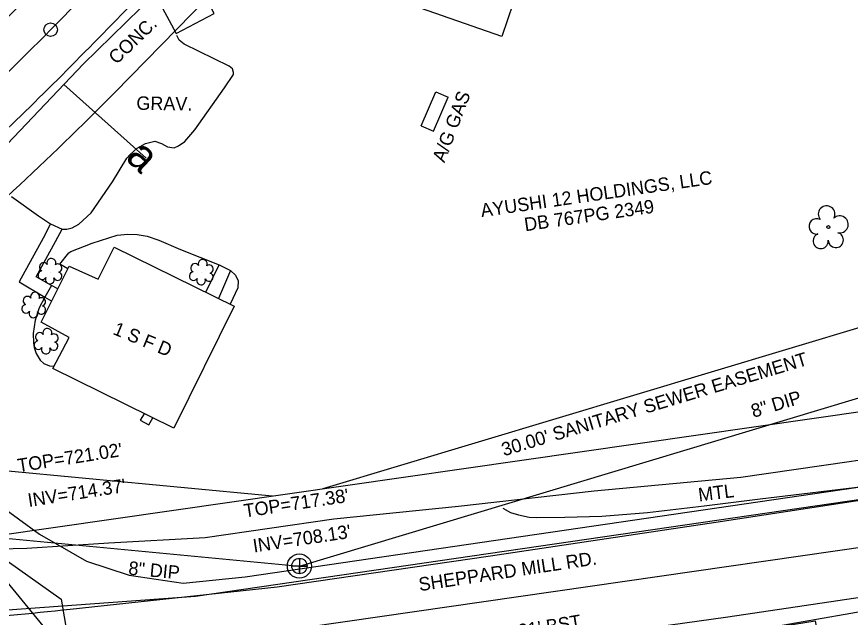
# Model space of a CAD drawing. Extents: x 1645945 to 2447332, y 713118 to 970361.
# Drawn here: x 1646361.8 to 1646547.8, y 969454.4 to 969588.4 of the extents above; entities that cross this region are included whole.
import ezdxf

# ---------------------------------------------------------------- set-up
doc = ezdxf.new("R2010")
doc.units = 0
for name, color, linetype in [('Exist Building', 7, 'Continuous'), ('Exist Building Text', 7, 'Continuous'), ('Exist Guardrail', 7, 'Continuous'), ('Exist Guardrail Text', 7, 'Continuous'), ('Exist Horizontal Alignment', 7, 'Continuous'), ('Exist Horizontal Alignment Station Label', 7, 'Continuous'), ('Exist Other Culture AG Tank', 7, 'Continuous'), ('Exist Other Culture AG Tank Text', 7, 'Continuous'), ('Exist Other Culture Area Outline', 7, 'Continuous'), ('Exist Other Culture Area Outline Text', 7, 'Continuous'), ('Exist Property Deed Book Text', 7, 'Continuous'), ('Exist Property Owner Text', 7, 'Continuous'), ('Exist Right of Way Easement Line', 7, 'Continuous'), ('Exist Right of Way Easement Line Text', 7, 'Continuous'), ('Exist Right of Way Line', 7, 'Continuous'), ('Exist Roads EOP', 7, 'Continuous'), ('Exist Roads EOP Text', 7, 'Continuous'), ('Exist Roads Soil', 7, 'Continuous'), ('Exist Roads Soil Text', 7, 'Continuous'), ('Exist Structure Minor Pipes RCP 18 Inch', 7, 'Continuous'), ('Exist Utilities Sanitary Sewer Manhole CELL', 7, 'Continuous'), ('Exist Utilities Sanitary Sewer Manhole Top Elevation', 7, 'Continuous'), ('Exist Utilities Sanitary Sewer UG Line', 7, 'Continuous'), ('Exist Utilities Sanitary Sewer UG Line Invert Elevation', 7, 'Continuous'), ('Exist Utilities Sanitary Sewer UG Line Text', 7, 'Continuous'), ('Exist Utilities Telephone UG Cable SUE LOS C', 7, 'Continuous'), ('Exist Utilities Telephone UG Conduit SUE LOS B', 7, 'Continuous'), ('Exist Utilities Telephone UG FO SUE LOS C', 7, 'Continuous'), ('Exist Utilities Water Meter CELL', 7, 'Continuous'), ('Exist Utilities Water UG Line SUE LOS B', 7, 'Continuous'), ('Exist Utilities Water UG Line SUE LOS C', 7, 'Continuous'), ('Exist Vegetation Shrub CELL', 7, 'Continuous'), ('Exist Vegetation Tree CELL', 7, 'Continuous')]:
    doc.layers.add(name, color=color, linetype=linetype)

msp = doc.modelspace()

# ---------------------------------------------------------------- linework, layer by layer
at = {"layer": 'Exist Building'}
for points in [[(1646470.02, 969583.99), (1646438.6, 969594.98), (1646445.1, 969613.68), (1646476.38, 969602.62)], [(1646410.32, 969523.79), (1646396.83, 969496.56), (1646369.82, 969509.94), (1646373.44, 969516.79), (1646367.24, 969520.22), (1646373.48, 969532.73), (1646379.92, 969529.81), (1646383.54, 969536.96)]]:
    msp.add_lwpolyline(points, close=True, dxfattribs=at)
at = {"layer": 'Exist Guardrail'}
for points in [[(1646470.26, 969478.73), (1646471.95, 969477.82), (1646473.74, 969477.24), (1646476.14, 969476.78), (1646477.86, 969476.66), (1646484.1, 969476.72), (1646492.35, 969476.96), (1646502.55, 969477.78), (1646515.16, 969479.3), (1646527.66, 969480.85), (1646552.44, 969483.79), (1646583.27, 969487.45), (1646605.12, 969490.42), (1646611.18, 969491.34), (1646616.77, 969492.33)], [(1646620.15, 969467.73), (1646608.6, 969466.17), (1646598.74, 969464.76), (1646580.79, 969461.39), (1646556.85, 969456.85), (1646531.28, 969452.35), (1646475.87, 969443.26), (1646432.85, 969436.42), (1646414.57, 969433.47), (1646402.18, 969431.21), (1646389.91, 969428.75), (1646383.65, 969427.16), (1646377.73, 969425.47), (1646371.72, 969423.8), (1646365.89, 969422.14), (1646363.88, 969421.49)]]:
    msp.add_lwpolyline(points, dxfattribs=at)
at = {"layer": 'Exist Horizontal Alignment'}
for p, q in [((1646418.81, 969635.96), (1646369.34, 969585.48)), ((1646298.92, 969433.93), (1647141.43, 969555.05))]:
    msp.add_line(p, q, dxfattribs=at)
msp.add_arc((1645951.5, 969994.91), 585, 309.61403, 315.58305, dxfattribs=at)
at = {"layer": 'Exist Horizontal Alignment Station Label'}
msp.add_circle((1646369.34, 969585.48), 1.5, dxfattribs=at)
at = {"layer": 'Exist Other Culture AG Tank'}
for p, q in [((1646452, 969564.02), (1646455.31, 969571.6)), ((1646454.75, 969562.82), (1646458.05, 969570.4)), ((1646455.31, 969571.6), (1646458.05, 969570.4)), ((1646452, 969564.02), (1646454.75, 969562.82))]:
    msp.add_line(p, q, dxfattribs=at)
at = {"layer": 'Exist Other Culture Area Outline'}
msp.add_lwpolyline([(1646397.32, 969584.61), (1646405.82, 969589.12), (1646401.24, 969597.74), (1646392.75, 969593.23), (1646397.32, 969584.61)], close=True, dxfattribs=at)
for points in [[(1646369.28, 969542.17), (1646367.71, 969538.98), (1646362.33, 969529.26), (1646368.06, 969525.79)], [(1646369.54, 969528.39), (1646366.13, 969530.36), (1646370.41, 969538.25), (1646371.95, 969540.99)], [(1646373.19, 969532.16), (1646371.37, 969533.21), (1646373.38, 969535.72), (1646373.85, 969536.04), (1646378.6, 969537.84), (1646384.18, 969539.65), (1646386.53, 969539.88), (1646388.64, 969539.79), (1646390.88, 969539.43), (1646393.47, 969538.54), (1646398.32, 969536.45), (1646406.93, 969533.01)], [(1646403.97, 969526.91), (1646406.93, 969533.01), (1646409.48, 969531.75), (1646406.81, 969525.51)], [(1646409.48, 969531.75), (1646410.61, 969530.76), (1646411.18, 969529.43), (1646411.1, 969527.9), (1646409.37, 969524.26)], [(1646370.95, 969527.66), (1646369.54, 969528.39), (1646368.06, 969525.79), (1646369.61, 969524.96)], [(1646368.06, 969525.79), (1646366.81, 969523.45), (1646365.88, 969520.72), (1646365.44, 969517.72), (1646365.5, 969515.61), (1646365.69, 969514.59), (1646366.1, 969513.23), (1646367.03, 969511.79), (1646367.85, 969511.05), (1646369.09, 969510.49), (1646370.08, 969510.44)], [(1646390.22, 969499.83), (1646389.31, 969498.38), (1646391.22, 969497.33), (1646392.13, 969498.89)]]:
    msp.add_lwpolyline(points, dxfattribs=at)
at = {"layer": 'Exist Right of Way Easement Line'}
for points in [[(1646430.19, 969483.11), (1646568.82, 969524.75)], [(1646336.92, 969489.25), (1646418.86, 969481.48)]]:
    msp.add_lwpolyline(points, dxfattribs=at)
at = {"layer": 'Exist Right of Way Line'}
for p, q in [((1646433.09, 969621.96), (1646383.63, 969571.48)), ((1646341.77, 969470.4), (1647145.86, 969586))]:
    msp.add_line(p, q, dxfattribs=at)
msp.add_arc((1645951.5, 969994.91), 605, 309.61403, 315.58305, dxfattribs=at)
at = {"layer": 'Exist Roads EOP'}
for points in [[(1646615.85, 969490.95), (1646565.02, 969482.74), (1646517.77, 969475.58), (1646467.5, 969468.02), (1646419.87, 969461.1), (1646373.7, 969456.15)], [(1646618.95, 969468.72), (1646569.51, 969461.71), (1646520.43, 969454.45), (1646471.94, 969447.66), (1646422.86, 969439.84), (1646379.88, 969432.02)]]:
    msp.add_lwpolyline(points, dxfattribs=at)
for points in [[(1646384.59, 969614.07), (1646363.63, 969592.14), (1646351.92, 969580.65), (1646345.86, 969575.11), (1646339.73, 969569.64), (1646334.58, 969565.16), (1646329.36, 969560.75), (1646318.86, 969552), (1646315.45, 969549.18), (1646312.01, 969546.44), (1646308.49, 969543.75), (1646304.83, 969541.11), (1646302.42, 969539.76), (1646299.77, 969538.9), (1646294.52, 969539.25), (1646282.77, 969544.37), (1646279.95, 969545.5), (1646277.2, 969546.85), (1646276.76, 969547.14)], [(1646373.7, 969456.15), (1646346.78, 969454.01), (1646328.12, 969455.82), (1646313.73, 969464.34), (1646305.52, 969476.97), (1646302.12, 969486.35), (1646303.66, 969500.55), (1646311.37, 969513.37), (1646318.37, 969523.3), (1646325.82, 969532.44), (1646336.85, 969542.47), (1646347.88, 969552.31), (1646363.63, 969567.2), (1646396.16, 969600.3)]]:
    msp.add_spline(points, degree=3, dxfattribs=at)
at = {"layer": 'Exist Roads Soil'}
msp.add_lwpolyline([(1646360.63, 969548.24), (1646366.62, 969543.99), (1646369.28, 969542.17), (1646371.95, 969540.99), (1646372.97, 969540.96), (1646374.12, 969541.26), (1646375.65, 969542.09), (1646378.42, 969544.65), (1646383.12, 969551.55), (1646386.36, 969556.81), (1646387.1, 969557.67), (1646388.65, 969559.04), (1646390.48, 969560.12), (1646392.59, 969560.58), (1646394.06, 969560.09), (1646395.41, 969559.35), (1646396.89, 969559.16), (1646397.9, 969559.6), (1646399.29, 969560.51), (1646401.53, 969563.16), (1646408.15, 969572.51), (1646410.11, 969575.48), (1646410.14, 969575.93), (1646409.95, 969576.76), (1646409.19, 969577.34), (1646399.11, 969582.29), (1646398.02, 969583.18), (1646397.48, 969584.17)], dxfattribs=at)
at = {"layer": 'Exist Structure Minor Pipes RCP 18 Inch'}
msp.add_line((1646289.57, 969546.84), (1646404.84, 969407.5), dxfattribs=at)
at = {"layer": 'Exist Utilities Sanitary Sewer Manhole CELL'}
msp.add_lwpolyline([(1646424.85, 969467.56), (1646424.85, 969464.13), (1646424.85, 969465.85), (1646426.57, 969465.85), (1646423.14, 969465.85)], dxfattribs=at)
for radius in [2.69, 1.71]:
    msp.add_circle((1646424.85, 969465.85), radius, dxfattribs=at)
at = {"layer": 'Exist Utilities Sanitary Sewer UG Line'}
msp.add_lwpolyline([(1646327.92, 969475.04), (1646424.85, 969465.85), (1646580.36, 969512.56)], dxfattribs=at)
at = {"layer": 'Exist Utilities Telephone UG Cable SUE LOS C'}
msp.add_lwpolyline([(1646348.02, 969486.6), (1646366.85, 969472.94), (1646377.35, 969466.91), (1646386.89, 969463.79), (1646398.95, 969462.04), (1646412.76, 969463.41), (1646611.06, 969492.42), (1646611.12, 969496.71)], dxfattribs=at)
at = {"layer": 'Exist Utilities Telephone UG Conduit SUE LOS B'}
msp.add_lwpolyline([(1646348.59, 969469.48), (1646364.06, 969469.8), (1646382.29, 969471.02), (1646403.86, 969472.18), (1646432.55, 969476.38), (1646460.38, 969479.2), (1646490.63, 969482.6), (1646523.38, 969485.68), (1646547.51, 969489.15), (1646567.59, 969492.12)], dxfattribs=at)
at = {"layer": 'Exist Utilities Telephone UG FO SUE LOS C'}
msp.add_lwpolyline([(1646264.86, 969462.15), (1646273.24, 969462.6), (1646331.74, 969455.12), (1646359.82, 969456.07), (1646401.7, 969459.13), (1646565.45, 969482.97), (1646568.22, 969483.91), (1646570.89, 969486.36), (1646573.89, 969488.03), (1646577, 969489.47), (1646583.56, 969490.7), (1646611.12, 969496.71)], dxfattribs=at)
at = {"layer": 'Exist Utilities Water UG Line SUE LOS B'}
msp.add_lwpolyline([(1646353.96, 969554.05), (1646376.58, 969577.81), (1646398.98, 969599.72), (1646421.44, 969623.58), (1646430.02, 969632.82), (1646453.53, 969657.83), (1646482.44, 969687.58), (1646504.67, 969710.19), (1646505.36, 969709.45), (1646509.94, 969704.89)], dxfattribs=at)
at = {"layer": 'Exist Utilities Water UG Line SUE LOS C'}
msp.add_line((1646372.27, 969573.28), (1646390.68, 969556.81), dxfattribs=at)
msp.add_lwpolyline([(1646354.93, 969470.25), (1646371.68, 969458.45), (1646376.94, 969427.38), (1646526.58, 969451.43), (1646539.94, 969453.64), (1646540.7, 969449.56)], dxfattribs=at)
at = {"layer": 'Exist Vegetation Shrub CELL'}
for p, q in [((1646369.28, 969531.43), (1646369.28, 969531.43)), ((1646403.04, 969531.21), (1646403.04, 969531.21)), ((1646365.64, 969523.9), (1646365.64, 969523.9)), ((1646368.4, 969515.82), (1646368.4, 969515.82))]:
    msp.add_line(p, q, dxfattribs=at)
for centre, radius, start, end in [((1646367.8, 969532.56), 0.968, 35.8908, 245.4216), ((1646369.51, 969533.47), 0.99, 334.8391, 200.4717), ((1646370.95, 969532.3), 0.929, 284.4567, 126.0861), ((1646401.56, 969532.34), 0.968, 35.8908, 245.4216), ((1646403.27, 969533.25), 0.99, 334.8391, 200.4717), ((1646367.48, 969530.73), 0.955, 95.1099, 327.9534), ((1646370.92, 969530.5), 0.937, 204.9913, 73.4601), ((1646401.24, 969530.51), 0.955, 95.1099, 327.9534), ((1646404.72, 969532.08), 0.929, 284.4567, 126.0861), ((1646369.15, 969529.75), 0.984, 151.2797, 21.387), ((1646402.91, 969529.53), 0.984, 151.2797, 21.387), ((1646404.68, 969530.28), 0.937, 204.9913, 73.4601), ((1646364.16, 969525.03), 0.968, 35.8908, 245.4216), ((1646365.87, 969525.94), 0.99, 334.8391, 200.4717), ((1646367.31, 969524.77), 0.929, 284.4567, 126.0861), ((1646363.84, 969523.2), 0.955, 95.1099, 327.9534), ((1646367.27, 969522.97), 0.937, 204.9913, 73.4601), ((1646365.51, 969522.22), 0.984, 151.2797, 21.387), ((1646368.62, 969517.86), 0.99, 334.8391, 200.4717), ((1646366.91, 969516.95), 0.968, 35.8908, 245.4216), ((1646370.07, 969516.69), 0.929, 284.4567, 126.0861), ((1646366.6, 969515.12), 0.955, 95.1099, 327.9534), ((1646368.27, 969514.14), 0.984, 151.2797, 21.387), ((1646370.03, 969514.9), 0.937, 204.9913, 73.4601)]:
    msp.add_arc(centre, radius, start, end, dxfattribs=at)
at = {"layer": 'Exist Vegetation Tree CELL'}
msp.add_line((1646542.88, 969541.46), (1646542.88, 969541.46), dxfattribs=at)
msp.add_circle((1646542.88, 969541.46), 0.326, dxfattribs=at)
for centre, radius, start, end in [((1646542.5, 969544.33), 1.86, 330.1651, 219.7134), ((1646540.28, 969541.61), 1.73, 62.6636, 279.3457), ((1646545.43, 969542.05), 1.9, 257.1011, 134.1999), ((1646541.18, 969538.34), 1.69, 111.5671, 6.231), ((1646544.55, 969538.56), 1.7, 181.2822, 74.56)]:
    msp.add_arc(centre, radius, start, end, dxfattribs=at)

# ---------------------------------------------------------------- texts
at = {"layer": 'Exist Building Text'}
msp.add_text('1 S F D', height=3, rotation=337.6287, dxfattribs=at).set_placement((1646383.04, 969517.63))
at = {"layer": 'Exist Guardrail Text'}
msp.add_text('MTL', height=3, rotation=7.0604, dxfattribs=at).set_placement((1646514.03, 969480.24))
at = {"layer": 'Exist Other Culture AG Tank Text'}
msp.add_text('A/G GAS', height=3, rotation=69.1565, dxfattribs=at).set_placement((1646457.22, 969555.66))
at = {"layer": 'Exist Other Culture Area Outline Text'}
msp.add_text('CONC.', height=3, rotation=43.7813, dxfattribs=at).set_placement((1646384.02, 969577.58))
at = {"layer": 'Exist Property Deed Book Text'}
msp.add_text('DB 767PG 2349', height=3, rotation=8.183, dxfattribs=at).set_placement((1646475.25, 969540.51))
at = {"layer": 'Exist Property Owner Text'}
msp.add_text('AYUSHI 12 HOLDINGS, LLC', height=3, rotation=8.183, dxfattribs=at).set_placement((1646465.51, 969543.66))
at = {"layer": 'Exist Right of Way Easement Line Text'}
msp.add_text("30.00' SANITARY SEWER EASEMENT", height=3, rotation=16.7193, dxfattribs=at).set_placement((1646470.48, 969490.31))
at = {"layer": 'Exist Roads EOP Text'}
for s, rotation, p in [('SHEPPARD MILL RD.', 8.5933, (1646451.69, 969460.22)), ("SR 1674   21' BST", 9.1804, (1646455.2, 969446.81))]:
    msp.add_text(s, height=3, rotation=rotation, dxfattribs=at).set_placement(p)
at = {"layer": 'Exist Roads Soil Text'}
msp.add_text('GRAV.', height=3, rotation=359.1691, dxfattribs=at).set_placement((1646388.46, 969567.62))
at = {"layer": 'Exist Utilities Sanitary Sewer Manhole Top Elevation'}
for s, rotation, p in [("TOP=721.02'", 8.8646, (1646362.17, 969486.74)), ("TOP=717.38'", 8.6041, (1646412.67, 969476.64))]:
    msp.add_text(s, height=3, rotation=rotation, dxfattribs=at).set_placement(p)
at = {"layer": 'Exist Utilities Sanitary Sewer UG Line Invert Elevation'}
for s, rotation, p in [("INV=714.37'", 8.8646, (1646364.48, 969479)), ("INV=708.13'", 8.6041, (1646414.71, 969468.85))]:
    msp.add_text(s, height=3, rotation=rotation, dxfattribs=at).set_placement(p)
at = {"layer": 'Exist Utilities Sanitary Sewer UG Line Text'}
for rotation, p in [(16.7193, (1646526.17, 969498.89)), (354.5815, (1646386.6, 969463.95))]:
    msp.add_text('8" DIP', height=3, rotation=rotation, dxfattribs=at).set_placement(p)
at = {"layer": 'Exist Utilities Water Meter CELL'}
msp.add_text('a', height=6.89, rotation=316.4007, dxfattribs=at).set_placement((1646385.81, 969556.69))

doc.saveas('drawing.dxf')
